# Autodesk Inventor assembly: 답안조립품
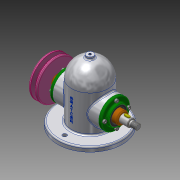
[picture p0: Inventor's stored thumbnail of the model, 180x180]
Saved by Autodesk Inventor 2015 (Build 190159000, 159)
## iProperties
Created: 2019-11
Part Number: 답안조립품
Document SubType Name: Assembly
Designer: Administrator
Author: Administrator
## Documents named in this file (11)
- C:\Users\Administrator.SC-201903271402\Desktop\491104V1026\답안조립품.iam
- C:\Users\Administrator.SC-201903271402\Desktop\491104V1026\본체.ipt
- C:\Users\Administrator.SC-201903271402\Desktop\491104V1026\축.ipt
- C:\Users\Administrator.SC-201903271402\Desktop\491104V1026\베어링 6203.ipt
- C:\Users\Administrator.SC-201903271402\Desktop\491104V1026\부시.ipt
- C:\Users\Administrator.SC-201903271402\Desktop\491104V1026\커버.ipt
- C:\Users\Administrator.SC-201903271402\Desktop\491104V1026\볼트 M4.ipt
- C:\Users\Administrator.SC-201903271402\Desktop\491104V1026\오일 실 26 38 8.ipt
- C:\Users\Administrator.SC-201903271402\Desktop\491104V1026\키 5x5x12.ipt
- C:\Users\Administrator.SC-201903271402\Desktop\491104V1026\V-벨트풀리.ipt
- V-벨트풀리.ipt
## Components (1 placed, 1 different names)
1. V-벨트풀리:1
